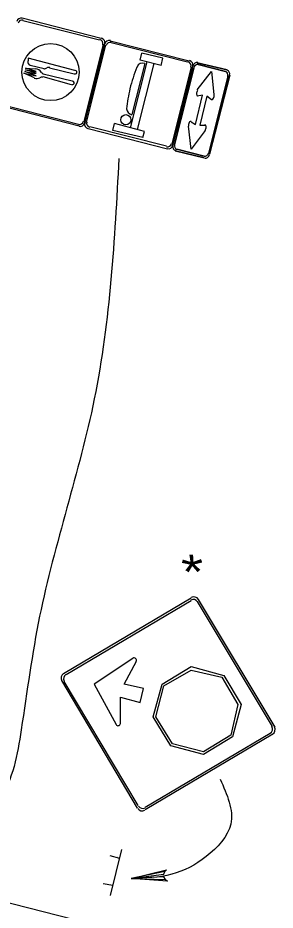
# Model space of a CAD drawing. Extents: x 640994 to 644422, y 298458 to 299646.
# Drawn here: x 643234.7 to 643271.2, y 299430.9 to 299557.6 of the extents above; entities that cross this region are included whole.
import ezdxf

# ---------------------------------------------------------------- set-up
doc = ezdxf.new("R2010")
doc.units = 0
doc.layers.add('2', color=7, linetype='Continuous')

msp = doc.modelspace()

# ---------------------------------------------------------------- linework, layer by layer
at = {"layer": '2'}
for p, q in [((643235.31, 299557.63), (643246.56, 299554.75)), ((643235.44, 299557.25), (643246.31, 299554.5)), ((643246.81, 299553.88), (643244.06, 299542.88)), ((643247.06, 299554), (643244.19, 299542.63)), ((643244.19, 299542.63), (643247.06, 299554)), ((643244.44, 299542.75), (643247.19, 299553.75)), ((643247.81, 299554.38), (643259.06, 299551.5)), ((643247.94, 299554.13), (643258.81, 299551.38)), ((643252.06, 299551.63), (643252.31, 299552.63)), ((643255.31, 299551.88), (643252.31, 299552.63)), ((643242.81, 299550.13), (643236.19, 299551.88)), ((643236.19, 299551.88), (643236.19, 299551.5)), ((643250.69, 299542), (643253.06, 299551.38)), ((643250.94, 299543.88), (643252.81, 299551.13)), ((643251.69, 299541.75), (643254.06, 299551.13)), ((643255.06, 299550.88), (643252.06, 299551.63)), ((643255.06, 299550.88), (643255.31, 299551.88)), ((643260.19, 299551.25), (643264.44, 299550.25)), ((643264.44, 299550.25), (643260.19, 299551.25)), ((643260.31, 299551), (643264.19, 299550)), ((643264.19, 299550), (643260.31, 299551)), ((643237.06, 299549.13), (643235.56, 299549.75)), ((643235.56, 299549.75), (643237.31, 299549.38)), ((643237.31, 299549.38), (643235.69, 299550)), ((643235.69, 299550), (643236.94, 299549.75)), ((643235.81, 299550.5), (643237.19, 299550.38)), ((643237.31, 299550), (643235.81, 299550.5)), ((643237.31, 299549.75), (643235.81, 299550.25)), ((643235.81, 299550.25), (643237.31, 299550)), ((643238.44, 299550.38), (643236.44, 299550.88)), ((643236.94, 299549.75), (643237.31, 299549.75)), ((643242.69, 299549.63), (643239.19, 299550.5)), ((643239.44, 299549.88), (643239.44, 299549.88)), ((643259.31, 299550.63), (643256.56, 299539.75)), ((643259.56, 299550.75), (643256.69, 299539.5)), ((643256.69, 299539.5), (643259.56, 299550.75)), ((643259.56, 299550.75), (643256.69, 299539.5)), ((643256.94, 299539.63), (643259.69, 299550.5)), ((643259.69, 299550.5), (643256.94, 299539.63)), ((643260.19, 299547.38), (643262.19, 299550)), ((643262.19, 299550), (643262.56, 299546.75)), ((643242.44, 299548.63), (643238.31, 299549.63)), ((643242.31, 299548.13), (643238.31, 299549.25)), ((643264.56, 299549.38), (643261.81, 299538.38)), ((643261.81, 299538.38), (643264.56, 299549.38)), ((643264.81, 299549.5), (643261.94, 299538.25)), ((643261.94, 299538.25), (643264.81, 299549.5)), ((643251.94, 299546.75), (643251.94, 299546.75)), ((643259.94, 299542.5), (643260.94, 299546.63)), ((643259.94, 299542.5), (643260.94, 299546.63)), ((643260.94, 299546.63), (643260.19, 299546.5)), ((643261.56, 299546.5), (643260.56, 299542.38)), ((643261.56, 299546.5), (643260.56, 299542.38)), ((643262.19, 299546), (643261.56, 299546.5)), ((643243.44, 299542.25), (643232.19, 299545.13)), ((643243.31, 299542.5), (643232.44, 299545.25)), ((643260.69, 299544.5), (643260.69, 299544.5)), ((643260.69, 299544.5), (643260.69, 299544.5)), ((643260.69, 299544.5), (643260.69, 299544.5)), ((643260.69, 299544.5), (643260.69, 299544.5)), ((643255.81, 299539.38), (643244.94, 299542.13)), ((643248.19, 299541.63), (643248.44, 299542.63)), ((643252.69, 299541.5), (643248.44, 299542.63)), ((643259.31, 299539), (643258.94, 299542.25)), ((643259.31, 299542.88), (643259.94, 299542.5)), ((643260.56, 299542.38), (643261.31, 299542.38)), ((643255.94, 299539), (643244.69, 299541.88)), ((643252.44, 299540.63), (643248.19, 299541.63)), ((643252.44, 299540.63), (643252.69, 299541.5)), ((643261.31, 299541.63), (643259.31, 299539)), ((643261.19, 299537.75), (643257.06, 299538.75)), ((643257.06, 299538.75), (643261.19, 299537.75)), ((643261.19, 299538), (643257.31, 299539)), ((643257.31, 299539), (643261.19, 299538)), ((643241.19, 299464.5), (643259.31, 299475.25)), ((643260.31, 299475), (643271.19, 299456.88)), ((643241.56, 299464.38), (643259.31, 299474.88)), ((643260.19, 299474.75), (643270.81, 299457)), ((643251.06, 299466.63), (643245.56, 299463)), ((643251.06, 299466.63), (643245.56, 299463)), ((643249.81, 299463), (643251.56, 299466.25)), ((643249.81, 299463), (643251.56, 299466.25)), ((643244.81, 299429), (643099.31, 299465.88)), ((643251.69, 299445.38), (643240.94, 299463.5)), ((643251.81, 299445.75), (643241.31, 299463.38)), ((643245.56, 299463), (643248.69, 299457.25)), ((643245.56, 299463), (643248.69, 299457.25)), ((643252.56, 299462.38), (643249.81, 299463)), ((643252.56, 299462.38), (643249.81, 299463)), ((643252.06, 299460.38), (643252.56, 299462.38)), ((643252.06, 299460.38), (643252.56, 299462.38)), ((643249.31, 299457.38), (643249.31, 299461.13)), ((643249.31, 299461.13), (643252.06, 299460.38)), ((643249.31, 299457.38), (643249.31, 299461.13)), ((643249.31, 299461.13), (643252.06, 299460.38)), ((643270.56, 299456), (643252.81, 299445.5)), ((643270.94, 299455.88), (643252.81, 299445.13)), ((643249.44, 299439.5), (643247.81, 299433)), ((643249.19, 299438.25), (643247.81, 299438.63)), ((643248.81, 299438.5), (643248.81, 299438.5)), ((643248.19, 299434.38), (643246.81, 299434.63))]:
    msp.add_line(p, q, dxfattribs=at)
for points in [[(643265.19, 299455.5), (643261.06, 299453), (643256.44, 299454.25), (643253.94, 299458.38), (643255.19, 299463), (643259.31, 299465.5), (643263.94, 299464.25), (643266.44, 299460.13), (643265.19, 299455.5)], [(643264.94, 299455.75), (643261.06, 299453.38), (643256.69, 299454.5), (643254.31, 299458.38), (643255.44, 299462.75), (643259.31, 299465), (643263.69, 299464), (643265.94, 299460.13), (643264.94, 299455.75)], [(643264.94, 299455.75), (643261.06, 299453.38), (643256.69, 299454.5), (643254.31, 299458.38), (643255.44, 299462.75), (643259.31, 299465), (643263.69, 299464), (643265.94, 299460.13), (643264.94, 299455.75)], [(643255.69, 299435.25), (643255.44, 299435.63), (643250.81, 299435.38), (643255.69, 299435.25), (643255.94, 299435), (643250.81, 299435.38), (643255.44, 299436), (643255.56, 299436.38), (643250.81, 299435.38), (643255.81, 299436.63), (643255.56, 299436.38)]]:
    msp.add_lwpolyline(points, dxfattribs=at)
for centre, radius in [((643239.36, 299549.93), 4.06), ((643250.05, 299543.16), 0.717)]:
    msp.add_circle(centre, radius, dxfattribs=at)
for centre, radius, start, end in [((643235.18, 299556.95), 0.645, 75.7754, 165.7754), ((643235.32, 299556.72), 0.597, 75.7754, 165.7754), ((643246.2, 299553.96), 0.597, 345.7754, 75.7754), ((643246.44, 299554.1), 0.645, 345.7754, 75.7754), ((643247.69, 299553.78), 0.645, 75.7754, 165.7754), ((643247.83, 299553.55), 0.597, 75.7754, 165.7754), ((643236.62, 299551.38), 0.507, 165.7754, 255.7754), ((643252.46, 299550.32), 0.888, 69.9409, 158.7047), ((643258.71, 299550.79), 0.597, 345.7754, 75.7754), ((643258.94, 299550.93), 0.645, 345.7754, 75.7754), ((643237.2, 299549.38), 0.996, 30.4773, 89.3124), ((643238.49, 299550.15), 0.504, 210.7055, 255.4294), ((643238.43, 299551.24), 0.835, 266.9017, 299.9124), ((643239.09, 299550.15), 0.443, 68.9162, 122.8856), ((643242.85, 299549.91), 0.261, 247.2807, 84.2701), ((643268.79, 299543.35), 18.64, 157.0049, 166.9537), ((643237.39, 299549.87), 0.869, 247.3155, 299.7154), ((643238.17, 299548.63), 0.593, 81.6072, 125.4072), ((643242.47, 299548.38), 0.234, 244.4009, 87.1499), ((643272.52, 299542.35), 22.5, 166.6162, 173.9535), ((643251.17, 299544.88), 1.04, 188.6173, 255.6836), ((643243.45, 299543.08), 0.597, 255.7754, 345.7754), ((643243.58, 299542.85), 0.645, 255.7754, 345.7754), ((643244.83, 299542.53), 0.645, 165.7754, 255.7754), ((643245.07, 299542.67), 0.597, 165.7754, 255.7754), ((643255.95, 299539.91), 0.597, 255.7754, 345.7754), ((643256.09, 299539.68), 0.645, 255.7754, 345.7754), ((643259.63, 299474.34), 0.69, 30.7754, 120.7754), ((643259.71, 299474.64), 0.753, 30.7754, 120.7754), ((643251.22, 299466.4), 0.326, 331.4732, 123.1918), ((643251.22, 299466.4), 0.326, 331.4732, 123.1918), ((643241.59, 299463.86), 0.753, 120.7754, 210.7754), ((643241.89, 299463.78), 0.69, 120.7754, 210.7754), ((643248.94, 299457.42), 0.326, 208.359, 0.0776), ((643248.94, 299457.42), 0.326, 208.359, 0.0776), ((643270.19, 299456.61), 0.69, 300.7754, 30.7754), ((643270.49, 299456.53), 0.753, 300.7754, 30.7754), ((643252.38, 299445.74), 0.753, 210.7754, 300.7754), ((643252.46, 299446.04), 0.69, 210.7754, 300.7754)]:
    msp.add_arc(centre, radius, start, end, dxfattribs=at)
for centre, major_axis, ratio, start_param, end_param in [((643260.09, 299550.64), (-0.158, -0.625), 0.833333, 3.141593, 4.712389), ((643260.09, 299550.64), (0.158, 0.625), 0.833333, 0, 1.570796), ((643260.2, 299550.42), (-0.147, -0.578), 0.833333, 3.141593, 4.712389), ((643260.2, 299550.42), (0.147, 0.578), 0.833333, 0, 1.570796), ((643264.05, 299549.44), (0.147, 0.578), 0.833333, 4.712389, 6.283185), ((643264.05, 299549.44), (0.147, 0.578), 0.833333, 4.712389, 6.283185), ((643264.26, 299549.58), (0.158, 0.625), 0.833333, 4.712389, 6.283185), ((643264.26, 299549.58), (0.158, 0.625), 0.833333, 4.712389, 6.283185), ((643260.32, 299547), (-0.113, -0.446), 0.5, 4.011799, 6.466875), ((643262.34, 299546.47), (-0.113, -0.446), 0.5, 6.078068, 8.589712), ((643259.17, 299542.47), (0.113, 0.446), 0.5, 6.099495, 8.554572), ((643261.2, 299541.98), (0.113, 0.446), 0.5, 3.976659, 6.488303), ((643257.44, 299539.53), (-0.147, -0.578), 0.833333, 4.712389, 6.283185), ((643257.44, 299539.53), (-0.147, -0.578), 0.833333, 4.712389, 6.283185), ((643257.24, 299539.39), (-0.158, -0.625), 0.833333, 4.712389, 6.283185), ((643257.24, 299539.39), (-0.158, -0.625), 0.833333, 4.712389, 6.283185), ((643261.3, 299538.55), (0.147, 0.578), 0.833333, 3.141593, 4.712389), ((643261.3, 299538.55), (-0.147, -0.578), 0.833333, 0, 1.570796), ((643261.4, 299538.33), (0.158, 0.625), 0.833333, 3.141593, 4.712389), ((643261.4, 299538.33), (-0.158, -0.625), 0.833333, 0, 1.570796)]:
    msp.add_ellipse(centre, major_axis=major_axis, ratio=ratio, start_param=start_param, end_param=end_param, dxfattribs=at)
for points in [[(643249.06, 299537.63), (643245.56, 299503.5), (643237.81, 299472.63), (643235.19, 299456.5), (643232.06, 299446.63), (643227.94, 299443.13), (643224.19, 299442.25), (643218.69, 299443.13)], [(643263.44, 299449.5), (643264.94, 299443.13), (643261.44, 299438.5), (643256.56, 299436), (643250.81, 299435.38)]]:
    msp.add_spline(points, degree=3, dxfattribs=at)

# ---------------------------------------------------------------- texts
msp.add_text('*', height=5.42, rotation=75.7789, dxfattribs=at).set_placement((643262.98, 299477.75))

doc.saveas('drawing.dxf')
